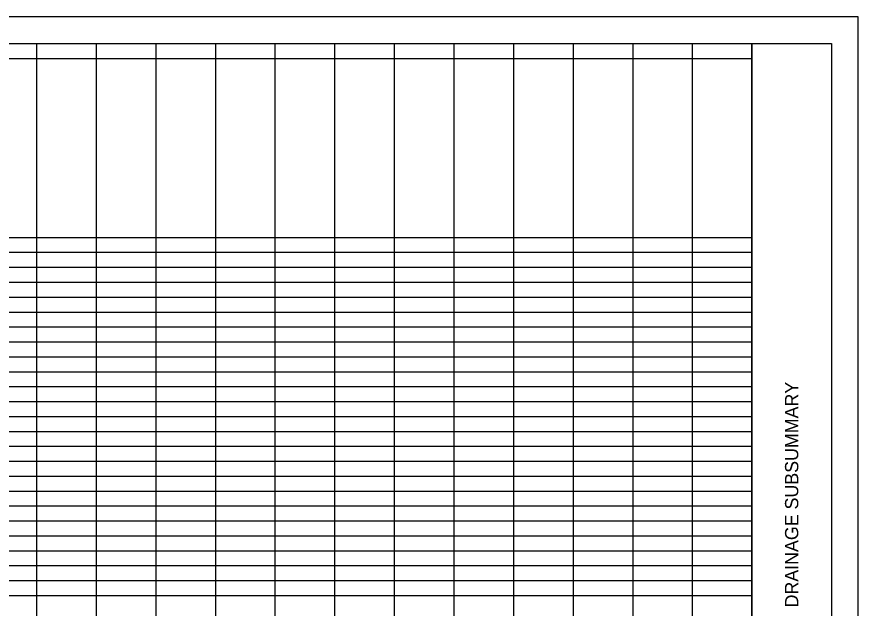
# Model space of a CAD drawing. Extents: x -0.1 to 36.9, y 0 to 22.
# Drawn here: x 18.07 to 33.88, y 10.88 to 21.98 of the extents above; entities that cross this region are included whole.
import ezdxf

# ---------------------------------------------------------------- set-up
doc = ezdxf.new("R2010")
doc.units = 0
for name, color, linetype in [('Default', 7, 'Continuous'), ('SH_Border', 7, 'Continuous'), ('SH_Cut_Line', 7, 'Continuous'), ('SH_Data', 7, 'Continuous')]:
    doc.layers.add(name, color=color, linetype=linetype)

msp = doc.modelspace()

# ---------------------------------------------------------------- linework, layer by layer
at = {"layer": 'Default'}
for p, q in [((1.376, 21.475), (31.879, 21.475)), ((18.439, 21.475), (18.439, 0.475)), ((19.559, 21.475), (19.559, 0.475)), ((20.679, 21.475), (20.679, 0.475)), ((21.799, 21.475), (21.799, 0.475)), ((22.919, 21.475), (22.919, 0.475)), ((24.039, 21.475), (24.039, 0.475)), ((25.159, 21.475), (25.159, 0.475)), ((26.279, 21.475), (26.279, 0.475)), ((27.399, 21.475), (27.399, 0.475)), ((28.519, 21.475), (28.519, 0.475)), ((29.639, 21.475), (29.639, 0.475)), ((30.759, 21.475), (30.759, 0.475)), ((31.879, 21.475), (31.879, 0.475)), ((8.359, 21.195), (31.879, 21.195)), ((8.359, 17.835), (31.879, 17.835)), ((1.376, 17.555), (31.879, 17.555)), ((1.376, 17.275), (31.879, 17.275)), ((1.376, 16.995), (31.879, 16.995)), ((1.376, 16.715), (31.879, 16.715)), ((1.376, 16.435), (31.879, 16.435)), ((1.376, 16.155), (31.879, 16.155)), ((1.376, 15.875), (31.879, 15.875)), ((1.376, 15.595), (31.879, 15.595)), ((1.376, 15.315), (31.879, 15.315)), ((1.376, 15.035), (31.879, 15.035)), ((1.376, 14.755), (31.879, 14.755)), ((1.376, 14.475), (31.879, 14.475)), ((1.376, 14.195), (31.879, 14.195)), ((1.376, 13.915), (31.879, 13.915)), ((1.376, 13.635), (31.879, 13.635)), ((1.376, 13.355), (31.879, 13.355)), ((1.376, 13.075), (31.879, 13.075)), ((1.376, 12.795), (31.879, 12.795)), ((1.376, 12.515), (31.879, 12.515)), ((1.376, 12.235), (31.879, 12.235)), ((1.376, 11.955), (31.879, 11.955)), ((1.376, 11.675), (31.879, 11.675)), ((1.376, 11.395), (31.879, 11.395)), ((1.376, 11.115), (31.879, 11.115))]:
    msp.add_line(p, q, dxfattribs=at)
at = {"layer": 'SH_Border'}
msp.add_line((31.876, 0.475), (31.876, 21.475), dxfattribs=at)
msp.add_lwpolyline([(1.376, 21.475), (33.376, 21.475), (33.376, 0.475), (1.376, 0.475)], close=True, dxfattribs=at)
at = {"layer": 'SH_Cut_Line'}
msp.add_lwpolyline([(-0.124, -0.025), (33.876, -0.025), (33.876, 21.975), (-0.124, 21.975)], close=True, dxfattribs=at)

# ---------------------------------------------------------------- texts
at = {"layer": 'SH_Data'}
msp.add_text('DRAINAGE SUBSUMMARY', height=0.25, rotation=90, dxfattribs=at).set_placement((32.751, 10.89))

doc.saveas('drawing.dxf')
